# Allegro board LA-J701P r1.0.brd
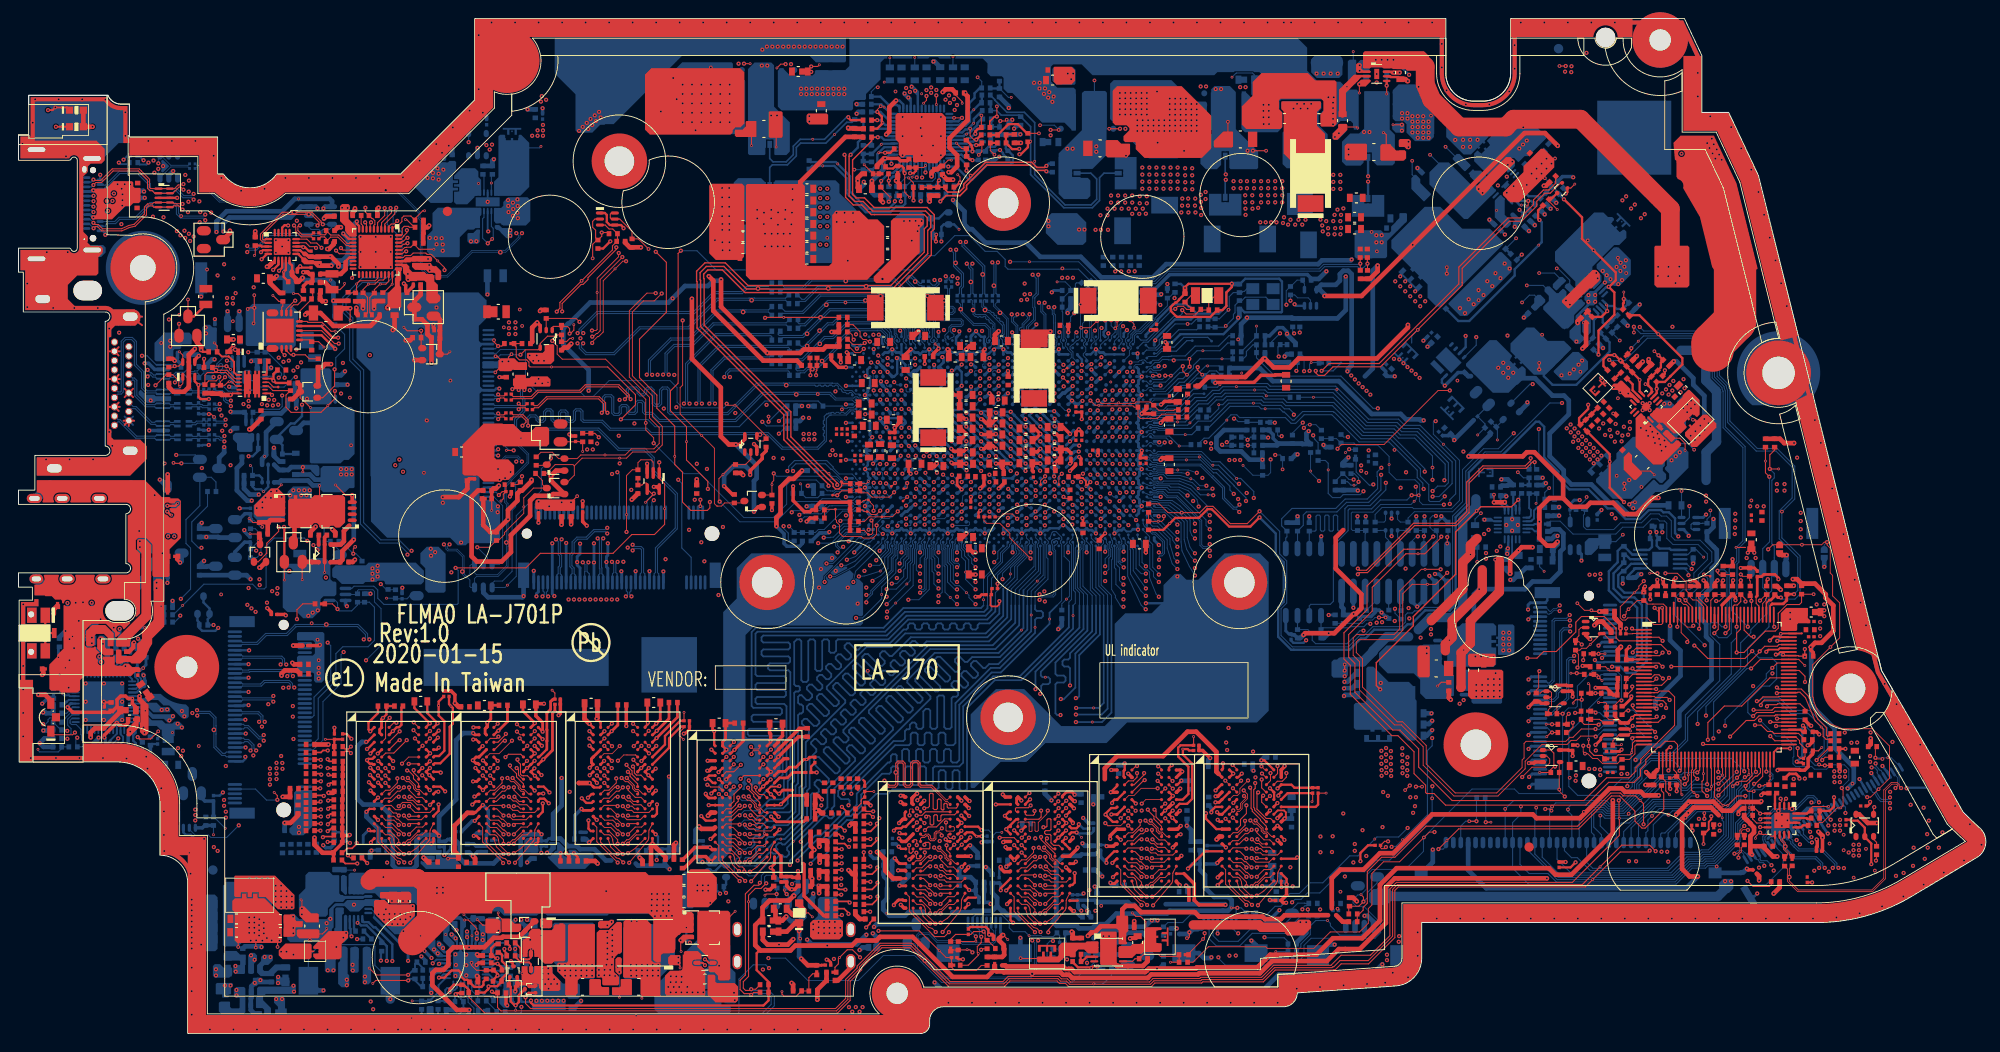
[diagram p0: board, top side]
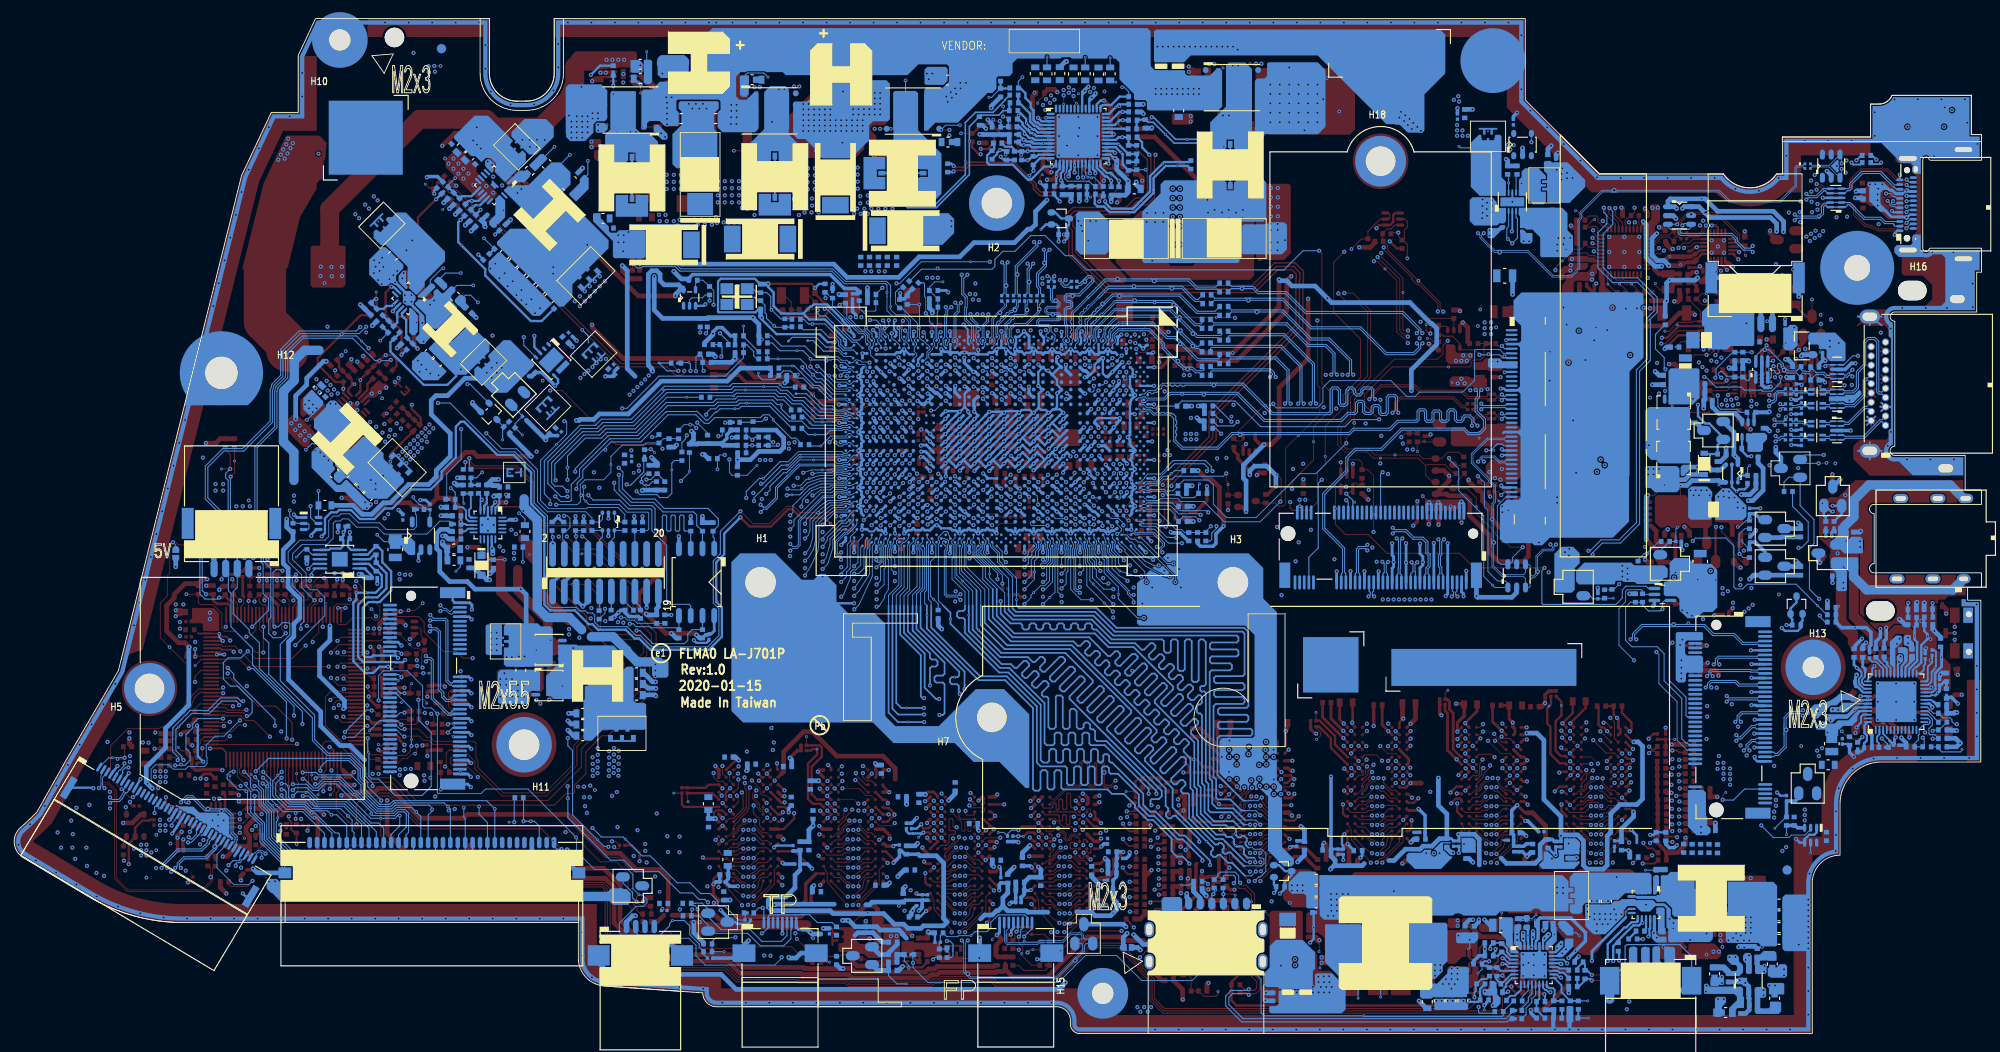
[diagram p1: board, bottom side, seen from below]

Outline 212.49 x 109.7 mm; copper layers: TOP, GND1, IN1, VCC, IN2, IN3, GND2, BOTTOM. Coordinates in mm from the lower left corner of the outline.

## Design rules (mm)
net group 8: nets EC_MUTE# PLUG_IN
net group AC: nets ACN ACP
net group DIFFPAIR12: nets N27490318 N27490324
net group DIFFPAIR13: nets VDDIO_MEM_S3_SENSE_H VDDIO_MEM_S3_SENSE_L
net group DIFFPAIR14: nets USBC0_SBU1_CONN USBC0_SBU2_CONN
net group EC_SMB_CK1: nets EC_SMB_CK1 EC_SMB_DA1
net group EC_SMB_CK2: nets EC_SMB_CK2 EC_SMB_DA2
net group I2C: nets USBC_I2C_SCL USBC_I2C_SDA
net group LPC-CLK: nets LPC_CLK0 LPC_CLK0_EC
net group PCIE_ARX_DTX_P7: nets PCIE_ARX_DTX_N7 PCIE_ARX_DTX_P7
net group PCIE_ATX_C_DRX_P7: nets PCIE_ATX_C_DRX_N7 PCIE_ATX_C_DRX_P7
net group PCIE_ATX_DRX_P7: nets PCIE_ATX_DRX_N7 PCIE_ATX_DRX_P7
net group REMOTE3: nets REMOTE3+ REMOTE3-
net group SINGLE-LED: nets BATT_CHG_LED# BATT_LOW_LED#
net group SINGLE-PROCHOT#: nets H_PROCHOT# VCOUT1_PROCHOT#
net group SINGLE-SVT: nets APU_SVT APU_SVT_R
net group SPK_L: nets SPK_L1- SPK_L2+
net group SPK_R: nets SPK_R1- SPK_R2+
net group SR: nets SRN SRP
net group 12.6VB_DDR: nets +12.6VB_DDR
net group 15: nets 3V/5VALW_PG 3V_FB 3V_FB_1 5V_3V_EN 5V_FB 5V_FB_1 EC_FAN_PWM1 EC_ON EC_RST# EC_RX EC_TX ENLDO_3V5V NOVO# TP_DISABLE# VCIN1_AC_IN
net group APU SENSE: nets APU_CORE_SEN_H APU_CORESOC_SEN_H APU_VDDP_S5_SEN_H APU_VDDP_S5_SEN_L APU_VSS_SEN_L
net group AUDIO: nets HPOUT_L1 HPOUT_R1 LDO2 LDO3 N31044849
net group CLK-PCIE: nets CLK_PCIE_SD CLK_PCIE_SD# CLK_PCIE_SSD1 CLK_PCIE_SSD1# CLK_PCIE_SSD2 CLK_PCIE_SSD2# CLK_PCIE_WLAN CLK_PCIE_WLAN#
net group CRYSTAL: nets 32K_X1 32K_X2 48M_X1 48M_X1_R 48M_X2 48M_X2_R RTC_CLK RTC_CLK_R SUSCLK_R
net group DDI-HDMI: nets APU_DP1_N0 APU_DP1_N1 APU_DP1_N2 APU_DP1_N3 APU_DP1_P0 APU_DP1_P1 APU_DP1_P2 APU_DP1_P3 HDMI_CLKN HDMI_CLKP HDMI_L_CLKN HDMI_L_CLKP HDMI_L_TX_N0 HDMI_L_TX_N1 HDMI_L_TX_N2 HDMI_L_TX_P0 HDMI_L_TX_P1 HDMI_L_TX_P2 HDMI_TX_N0 HDMI_TX_N1 HDMI_TX_N2 HDMI_TX_P0 HDMI_TX_P1 HDMI_TX_P2
net group DDR_A_CLK: nets DDR_A_CLK0#
net group DDR_A_CLK0: nets DDR_A_CLK0
net group DDR_A_CMD: nets DDR_A_ACT# DDR_A_BA0 DDR_A_BA1 DDR_A_BG0 DDR_A_BG1 DDR_A_BG1_R DDR_A_CAS# DDR_A_CKE0 DDR_A_CS0# DDR_A_MA0 DDR_A_MA1 DDR_A_MA2 DDR_A_MA3 DDR_A_MA4 DDR_A_MA5 DDR_A_MA6 DDR_A_MA7 DDR_A_MA8 DDR_A_MA9 DDR_A_MA10 DDR_A_MA11 DDR_A_MA12 DDR_A_MA13 DDR_A_ODT0 DDR_A_PAR DDR_A_RAS# DDR_A_WE#
net group DDR_A_DQ0: nets DDR_A_DM0 DDR_A_DQ0 DDR_A_DQ1 DDR_A_DQ2 DDR_A_DQ3 DDR_A_DQ4 DDR_A_DQ5 DDR_A_DQ6 DDR_A_DQ7
net group DDR_A_DQ1: nets DDR_A_DM1 DDR_A_DQ8 DDR_A_DQ9 DDR_A_DQ10 DDR_A_DQ11 DDR_A_DQ12 DDR_A_DQ13 DDR_A_DQ14 DDR_A_DQ15
net group DDR_A_DQ2: nets DDR_A_DM2 DDR_A_DQ16 DDR_A_DQ17 DDR_A_DQ18 DDR_A_DQ19 DDR_A_DQ20 DDR_A_DQ21 DDR_A_DQ22 DDR_A_DQ23
net group DDR_A_DQ3: nets DDR_A_DM3 DDR_A_DQ24 DDR_A_DQ25 DDR_A_DQ26 DDR_A_DQ27 DDR_A_DQ28 DDR_A_DQ29 DDR_A_DQ30 DDR_A_DQ31
net group DDR_A_DQ4: nets DDR_A_DM4 DDR_A_DQ32 DDR_A_DQ33 DDR_A_DQ34 DDR_A_DQ35 DDR_A_DQ36 DDR_A_DQ37 DDR_A_DQ38 DDR_A_DQ39
net group DDR_A_DQ5: nets DDR_A_DM5 DDR_A_DQ40 DDR_A_DQ41 DDR_A_DQ42 DDR_A_DQ43 DDR_A_DQ44 DDR_A_DQ45 DDR_A_DQ46 DDR_A_DQ47
net group DDR_A_DQ6: nets DDR_A_DM6 DDR_A_DQ48 DDR_A_DQ49 DDR_A_DQ50 DDR_A_DQ51 DDR_A_DQ52 DDR_A_DQ53 DDR_A_DQ54 DDR_A_DQ55
net group DDR_A_DQ7: nets DDR_A_DM7 DDR_A_DQ56 DDR_A_DQ57 DDR_A_DQ58 DDR_A_DQ59 DDR_A_DQ60 DDR_A_DQ61 DDR_A_DQ62 DDR_A_DQ63
net group DDR_A_DQS: nets DDR_A_DQS0# DDR_A_DQS1# DDR_A_DQS2# DDR_A_DQS3# DDR_A_DQS4# DDR_A_DQS5# DDR_A_DQS6# DDR_A_DQS7#
net group DDR_A_DQS0: nets DDR_A_DQS0
net group DDR_A_DQS1: nets DDR_A_DQS1
net group DDR_A_DQS2: nets DDR_A_DQS2
net group DDR_A_DQS3: nets DDR_A_DQS3
net group DDR_A_DQS4: nets DDR_A_DQS4
net group DDR_A_DQS5: nets DDR_A_DQS5
net group DDR_A_DQS6: nets DDR_A_DQS6
net group DDR_A_DQS7: nets DDR_A_DQS7
net group DDR_A_MISCELLANEOUS: nets DDR_A_ALERT# DDR_A_EVENT# DDR_A_RST#
net group DDR_B_CLK: nets DDR_B_CLK0#
net group DDR_B_CLK0: nets DDR_B_CLK0
net group DDR_B_CMD: nets DDR_B_ACT# DDR_B_BA0 DDR_B_BA1 DDR_B_BG0 DDR_B_BG1 DDR_B_BG1_R DDR_B_CAS# DDR_B_CKE0 DDR_B_CS0# DDR_B_MA0 DDR_B_MA1 DDR_B_MA2 DDR_B_MA3 DDR_B_MA4 DDR_B_MA5 DDR_B_MA6 DDR_B_MA7 DDR_B_MA8 DDR_B_MA9 DDR_B_MA10 DDR_B_MA11 DDR_B_MA12 DDR_B_MA13 DDR_B_ODT0 DDR_B_PAR DDR_B_RAS# DDR_B_WE#
net group DDR_B_DQ0: nets DDR_B_DM0 DDR_B_DQ0 DDR_B_DQ1 DDR_B_DQ2 DDR_B_DQ3 DDR_B_DQ4 DDR_B_DQ5 DDR_B_DQ6 DDR_B_DQ7
net group DDR_B_DQ1: nets DDR_B_DM1 DDR_B_DQ8 DDR_B_DQ9 DDR_B_DQ10 DDR_B_DQ11 DDR_B_DQ12 DDR_B_DQ13 DDR_B_DQ14 DDR_B_DQ15
net group DDR_B_DQ2: nets DDR_B_DM2 DDR_B_DQ16 DDR_B_DQ17 DDR_B_DQ18 DDR_B_DQ19 DDR_B_DQ20 DDR_B_DQ21 DDR_B_DQ22 DDR_B_DQ23
net group DDR_B_DQ3: nets DDR_B_DM3 DDR_B_DQ24 DDR_B_DQ25 DDR_B_DQ26 DDR_B_DQ27 DDR_B_DQ28 DDR_B_DQ29 DDR_B_DQ30 DDR_B_DQ31
net group DDR_B_DQ4: nets DDR_B_DM4 DDR_B_DQ32 DDR_B_DQ33 DDR_B_DQ34 DDR_B_DQ35 DDR_B_DQ36 DDR_B_DQ37 DDR_B_DQ38 DDR_B_DQ39
net group DDR_B_DQ5: nets DDR_B_DM5 DDR_B_DQ40 DDR_B_DQ41 DDR_B_DQ42 DDR_B_DQ43 DDR_B_DQ44 DDR_B_DQ45 DDR_B_DQ46 DDR_B_DQ47
net group DDR_B_DQ6: nets DDR_B_DM6 DDR_B_DQ48 DDR_B_DQ49 DDR_B_DQ50 DDR_B_DQ51 DDR_B_DQ52 DDR_B_DQ53 DDR_B_DQ54 DDR_B_DQ55
net group DDR_B_DQ7: nets DDR_B_DM7 DDR_B_DQ56 DDR_B_DQ57 DDR_B_DQ58 DDR_B_DQ59 DDR_B_DQ60 DDR_B_DQ61 DDR_B_DQ62 DDR_B_DQ63
net group DDR_B_DQS: nets DDR_B_DQS0# DDR_B_DQS1# DDR_B_DQS2# DDR_B_DQS3# DDR_B_DQS4# DDR_B_DQS5# DDR_B_DQS6# DDR_B_DQS7#
net group DDR_B_DQS0: nets DDR_B_DQS0
net group DDR_B_DQS1: nets DDR_B_DQS1
net group DDR_B_DQS2: nets DDR_B_DQS2
net group DDR_B_DQS3: nets DDR_B_DQS3
net group DDR_B_DQS4: nets DDR_B_DQS4
net group DDR_B_DQS5: nets DDR_B_DQS5
net group DDR_B_DQS6: nets DDR_B_DQS6
net group DDR_B_DQS7: nets DDR_B_DQS7
net group DDR_B_MISCELLANEOUS: nets DDR_B_ALERT# DDR_B_EVENT# DDR_B_RST#
net group DP-AUX: nets APU_DP1_CTRL_CLK APU_DP1_CTRL_DAT EDP_AUXN EDP_AUXN_C EDP_AUXP EDP_AUXP_C HDMI_CTRL_CLK HDMI_CTRL_DAT USBC0_AUXN USBC0_AUXP USBC0_C_AUXN USBC0_C_AUXP USBC0_SBU1 USBC0_SBU2
net group EDP: nets EDP_TXN0 EDP_TXN0_C EDP_TXN1 EDP_TXN1_C EDP_TXP0 EDP_TXP0_C EDP_TXP1 EDP_TXP1_C
net group HDA: nets HDA_BIT_CLK HDA_BIT_CLK_R HDA_RST# HDA_SDIN0 HDA_SDIN0_R HDA_SDOUT HDA_SDOUT_R HDA_SYNC HDA_SYNC_R
net group HP: nets HP_OUTL HP_OUTR HPOUT_L HPOUT_R
net group LED: nets BATT_CHG_LED#_R2 BATT_LOW_LED#_R2 CAPS_LED#
net group LPC: nets CLKRUN# EC_SCI# LPC_AD0 LPC_AD0_R LPC_AD1 LPC_AD1_R LPC_AD2 LPC_AD2_R LPC_AD3 LPC_AD3_R LPC_FRAME# LPC_RST# LPC_RST#_R LPCPD# SERIRQ
net group PCIE: nets PCIE_ARX_DTX_N0 PCIE_ARX_DTX_N1 PCIE_ARX_DTX_N2 PCIE_ARX_DTX_N3 PCIE_ARX_DTX_N8 PCIE_ARX_DTX_N9 PCIE_ARX_DTX_N10 PCIE_ARX_DTX_N11 PCIE_ARX_DTX_P0 PCIE_ARX_DTX_P1 PCIE_ARX_DTX_P2 PCIE_ARX_DTX_P3 PCIE_ARX_DTX_P8 PCIE_ARX_DTX_P9 PCIE_ARX_DTX_P10 PCIE_ARX_DTX_P11 PCIE_ATX_C_DRX_N0 PCIE_ATX_C_DRX_N1 PCIE_ATX_C_DRX_N2 PCIE_ATX_C_DRX_N3 PCIE_ATX_C_DRX_N8 PCIE_ATX_C_DRX_N9 PCIE_ATX_C_DRX_N10 PCIE_ATX_C_DRX_N11 PCIE_ATX_C_DRX_P0 PCIE_ATX_C_DRX_P1 PCIE_ATX_C_DRX_P2 PCIE_ATX_C_DRX_P3 PCIE_ATX_C_DRX_P8 PCIE_ATX_C_DRX_P9 PCIE_ATX_C_DRX_P10 PCIE_ATX_C_DRX_P11 PCIE_ATX_DRX_N0 PCIE_ATX_DRX_N1 PCIE_ATX_DRX_N2 PCIE_ATX_DRX_N3 PCIE_ATX_DRX_N8 PCIE_ATX_DRX_N9 PCIE_ATX_DRX_N10 PCIE_ATX_DRX_N11 PCIE_ATX_DRX_P0 PCIE_ATX_DRX_P1 PCIE_ATX_DRX_P2 PCIE_ATX_DRX_P3 PCIE_ATX_DRX_P8 PCIE_ATX_DRX_P9 PCIE_ATX_DRX_P10 PCIE_ATX_DRX_P11
net group PCIE-ONBOARD: nets PCIE_ARX_DTX_N5 PCIE_ARX_DTX_P5 PCIE_ATX_C_DRX_N5 PCIE_ATX_C_DRX_P5 PCIE_ATX_DRX_N5 PCIE_ATX_DRX_P5
net group S20: nets PWR_LED#
net group SINGLE-ALERT: nets APU_ALERT#
net group SINGLE-BEEP: nets BEEP# HDA_SPKR PC_BEEP
net group SINGLE-BT/WLAN: nets APU_BT_OFF# APU_WL_OFF# WL_RST#
net group SINGLE-DISPLAY: nets ENBKL ENBKL_R ENVDD INVTPWM INVTPWM_R
net group SINGLE-DMIC: nets DMIC_CLK0_APU DMIC_DAT0_APU SOC_DMIC_CLK0 SOC_DMIC_DAT0
net group SINGLE-DP: nets APU_DP1_HPD EDP_HPD EDP_HPD_R HDMI_HPD USBC0_PD_HPD
net group SINGLE-HDT: nets APU_DBREQ# APU_TCK APU_TDI APU_TDO APU_TMS APU_TRST# APU_TRST#_R
net group SINGLE-KB: nets KB_RST#
net group SINGLE-PCIE_REQ: nets CLKREQ_SD# CLKREQ_SSD1# CLKREQ_WLAN# CLKREQ_WLAN#_R
net group SINGLE-SENSOR: nets LID_SW#
net group SINGLE-SEQUENCE: nets AC_PRESENT APU_FCH_PWRGD_R APU_PCIE0_RST# APU_PCIE1_RST# APU_PCIE_RST# APU_PCIE_RST#_R APU_PCIE_WAKE# APU_PWRGD APU_RST# APU_RST#_EC EC_LOW_BATT# EC_RSMRST# EC_THERMTRIP# FP_GPIO_AL0 ON/OFF# PBTN_OUT# PM_SLP_S3# PM_SLP_S5# S0A3_GPIO S0I3_EC# SSD1_PWR_EN# SSD2_PWR_EN# SUSP# SYS_PWRGD_EC SYS_RESET# VR_ON
net group SINGLE-SVC: nets APU_SVC
net group SINGLE-SVD: nets APU_SVD
net group SINGLE-TEST POINT: nets APU_TEST4 APU_TEST5 APU_TEST14 APU_TEST15 APU_TEST16 APU_TEST17 APU_TEST31 APU_TEST41 APU_TEST470 APU_TEST471
net group SINGLE-USB_OC: nets USB_OC0# USB_OC0#_R USB_OC1#
net group SMBUS: nets EC_SMCA EC_SMDA SCL_CHG SDA_CHG
net group SPI: nets APU_SPI_CLK APU_SPI_CLK_R APU_SPI_CS1# APU_SPI_HOLD# APU_SPI_MISO APU_SPI_MOSI APU_SPI_WP#
net group SPK: nets SPK_L1-_CONN SPK_L2+_CONN SPK_R1-_CONN SPK_R2+_CONN
net group USB-20: nets CHR_USB20_N1 CHR_USB20_N1_R CHR_USB20_P1 CHR_USB20_P1_R USB20_N1 USB20_N2 USB20_N3 USB20_N5 USB20_N5_R USB20_N6 USB20_N7 USB20_P1 USB20_P2 USB20_P3 USB20_P5 USB20_P5_R USB20_P6 USB20_P7
net group USB-32: nets USBC0_ARX_C_DTX_N1 USBC0_ARX_C_DTX_N2 USBC0_ARX_C_DTX_P1 USBC0_ARX_C_DTX_P2 USBC0_ARX_DTX_N1 USBC0_ARX_DTX_N2 USBC0_ARX_DTX_P1 USBC0_ARX_DTX_P2 USBC0_ATX_C_DRX_N1 USBC0_ATX_C_DRX_N2 USBC0_ATX_C_DRX_P1 USBC0_ATX_C_DRX_P2 USBC0_ATX_DRX_N1 USBC0_ATX_DRX_N2 USBC0_ATX_DRX_P1 USBC0_ATX_DRX_P2
net group USB-C20: nets USB20_N0 USB20_N0_R USB20_P0 USB20_P0_R
net group USB-C31: nets USB3_ARX_DTX_N1 USB3_ARX_DTX_N2 USB3_ARX_DTX_P1 USB3_ARX_DTX_P2 USB3_ATX_DRX_N1 USB3_ATX_DRX_N2 USB3_ATX_DRX_P1 USB3_ATX_DRX_P2
net group W10S10: nets REMOTE1+ REMOTE2+ REMOTE-
net group W20: nets +1.8VALWP
net group W40: nets EXT_MIC_RING2 EXT_MIC_SLEEVE HGNDA HGNDB N31049415 N31049464
nets with their own width: min track width 0.102; nets SYSON
nets with their own width: min track width 0.254; nets +0.6VS +1.2V +3VL +APU_CORE ECAGND GND
nets with their own width: min track width 0.305; nets +1.8VDD_CODEC
nets with their own width: min track width 0.508; nets +0.6V_DDRB_VREFCA +0.75VALW +0.75VALW_0.75VS +0.75VALWP +0.75VS +1.2VP +1.8VALW +1.8VALW_1.8VS +1.8VS +2.5V +3V_DMIC +3V_FP +3VALW +3VALW_EC +3VDD_CODEC +3VS +3VS_SSD2 +3VS_TP +5V_IN_PWR +5VL +5VS_KBL +12.6VB_3V +12.6VB_5V +12.6VB_CPU +12.6VB_VDDP +19V_ADPIN +19V_VIN_P1 +20V_TBT_VBUS_L +APU_CORE_SOC +FLT1 +IOVDD_CODEC +LDO_3V3_5457V +LEDVDD +RTC_APU +RTCBATT +RTCBATT_R +USBC0_VBUS +VCC_IO2 GNDA VDDIO_AUDIO
nets with their own width: min track width 1.016; nets +0.6V_DDRA_VREFCA +5V_DISPLAY +5VALW_USB2 +5VS_FAN +5VS_PVDD +LCDVDD
nets with their own width: min track width 1.524; nets +LCDVDD_CONN
nets with their own width: min track width 2.032; nets +3VS_SSD1 +3VS_WLAN +5VDDA_CODEC
nets with their own width: min track width 2.54; nets +5VALW_USB1

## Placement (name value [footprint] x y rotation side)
C1  1U_0201_6.3V6M  [C_0201]  113.68 62.15 90 top
C3  4.7U_0402_6.3V6M  [C_0402]  52.68 71.85 270 top
C4  1U_0201_6.3V6M  [C_0201]  50.56 98.21 90 bottom
C7  4.7U_0805_25V6-K  [C_0805]  52.35 81.89 180 bottom
C8  0.1U_0201_10V6K  [C_0201]  53.23 66.44 180 top
C9  0.1U_0201_10V6K  [C_0201]  53.23 67.07 180 top
C10  0.1U_0201_10V6K  [C_0201]  55.52 67.43 180 top
C11  0.1U_0201_10V6K  [C_0201]  55.52 68.06 180 top
C12  0.1U_0201_10V6K  [C_0201]  53.23 69.11 180 top
C13  0.1U_0201_10V6K  [C_0201]  53.23 68.47 180 top
C67  0.1U_0201_10V6K  [C_0201]  192.8 29.74 270 top
C68  1000P_0402_50V7K  [C_0402]  176.64 27.78 270 top
C69  1000P_0402_50V7K  [C_0402]  173.66 40.4 180 top
C70  0.1U_0201_10V6K  [C_0201]  178.35 27.03 90 top
C71  0.1U_0201_10V6K  [C_0201]  51.69 87.76 270 bottom
C72  10U_0402_6.3V6M  [C_0402]  52.45 87.67 270 bottom
C73  10U_0402_6.3V6M  [C_0402]  55.82 98.96 90 bottom
C74  0.1U_0201_10V6K  [C_0201]  56.61 98.82 90 bottom
C75  1000P_0402_50V7K  [C_0402]  51.18 92.86 90 bottom
C76  2200P_0402_25V7K  [C_0402]  50.17 92.86 90 bottom
C77  0.1U_0201_10V6K  [C_0201]  49.66 87.25 270 bottom
C78  10U_0402_6.3V6M  [C_0402]  48.9 87.17 270 bottom
C79  10U_0402_6.3V6M  [C_0402]  46.84 94.05 90 bottom
C80  0.1U_0201_10V6K  [C_0201]  45.95 93.96 90 bottom
C84  4.7U_0402_6.3V6M  [C_0402]  177.02 47.44 90 top
C204  0.1U_0201_10V6K  [C_0201]  60.18 63.99 90 top
C229  0.1U_0201_10V6K  [C_0201]  181.31 22.51 180 top
C230  0.1U_0201_10V6K  [C_0201]  49.25 60.53 270 top
C231  10U_0402_6.3V6M  [C_0402]  48.48 60.66 270 top
C232  100P_0402_50V8J  [C_0402]  186.99 49.41 90 top
C233  0.1U_0201_10V6K  [C_0201]  176.25 47.48 90 top
C234  100P_0402_50V8J  [C_0402]  185.14 47.44 90 top
C235  0.1U_0201_10V6K  [C_0201]  193.36 44.53 0 top
C236  10U_0402_6.3V6M  [C_0402]  153.27 75.31 225 bottom
C237  0.1U_0201_10V K X5R  [C_0201]  152.62 75.75 225 bottom
C238  10U_0402_6.3V6M  [C_0402]  156.85 72.08 225 bottom
C239  0.1U_0201_10V K X5R  [C_0201]  157.3 71.46 225 bottom
C240  10U_0402_6.3V6M  [C_0402]  154.02 65.45 315 bottom
C241  0.1U_0201_10V K X5R  [C_0201]  153.4 65.03 315 bottom
C242  10U_0402_6.3V6M  [C_0402]  148.32 71.83 225 bottom
C243  0.1U_0201_10V K X5R  [C_0201]  147.75 72.32 225 bottom
C249  27P_0201_25V8  [C_0201]  52.65 58.57 0 top
C250  0.22U_0201_6.3V6M  [C_0201]  102.67 79.15 90 bottom
C251  0.22U_0201_6.3V6M  [C_0201]  103.34 79.16 90 bottom
C252  0.22U_0201_6.3V6M  [C_0201]  105.83 79.16 90 bottom
C253  0.22U_0201_6.3V6M  [C_0201]  105.2 79.16 90 bottom
C255  100P_0402_50V8J  [C_0402]  184.13 49.6 90 top
C256  220P_0201_25V7K  [C_0201]  173.63 43.2 180 top
C257  100P_0402_50V8J  [C_0402]  189.08 26.89 270 top
C258  0.1U_0201_10V K X5R  [C_0201]  187.81 49.97 270 top
C259  100P_0402_50V8J  [C_0402]  173.66 38.37 180 top
C260  100P_0402_50V8J  [C_0402]  173.21 29.62 270 top
C261  100P_0402_50V8J  [C_0402]  188.83 47.44 90 top
C265  100P_0402_50V8J  [C_0402]  183.24 47.44 90 top
C266  220P_0201_25V7K  [C_0201]  193.36 42.88 0 top
C267  100P_0402_50V8J  [C_0402]  181.46 48.35 270 top
C268  22P_0402_50V8J  [C_0402]  170.68 39.64 180 top
C269  0.1U_0201_10V6K  [C_0201]  171.53 30.49 0 top
C316  0.1U_0201_10V K X5R  [C_0201]  157.59 66.7 225 bottom
C317  100P_0402_50V8J  [C_0402]  196.65 29.86 180 top
C318  100P_0402_50V8J  [C_0402]  196.65 30.77 180 top
CA1  22P_0402_50V8J  [C_0402]  4.65 30.98 180 bottom
CA2  1000P_0402_50V7K  [C_0402]  24.17 3.05 0 bottom
CA3  1000P_0402_50V7K  [C_0402]  26 3.08 270 bottom
CA4  1000P_0402_50V7K  [C_0402]  24.22 8.26 90 bottom
CA5  1000P_0402_50V7K  [C_0402]  27.32 6.48 270 bottom
CA6  2.2U_0402_6.3V6M  [C_0402]  3.79 38.04 90 bottom
CA7  2.2U_0402_6.3V6M  [C_0402]  12.83 41.57 270 bottom
CA8  2.2U_0402_6.3V6M  [C_0402]  13.77 41.57 270 bottom
CA9  2.2U_0402_6.3V6M  [C_0402]  10.52 41.62 270 bottom
CA10  1U_0201_6.3V6M  [C_0201]  6.07 41.08 270 bottom
CA11  1U_0201_6.3V6M  [C_0201]  5.34 40.86 90 bottom
CA12  4.7U_0402_6.3V6M  [C_0402]  14.25 32.07 270 bottom
CA13  0.1U_0201_10V6K  [C_0201]  15.03 31.87 270 bottom
CA14  2.2U_0402_6.3V6M  [C_0402]  4.42 42.7 270 bottom
CA15  2.2U_0402_6.3V6M  [C_0402]  3.76 35.53 0 bottom
CA16  1000P_0402_50V7K  [C_0402]  10.82 40.28 180 top
CA17  1000P_0402_50V7K  [C_0402]  11.69 42.18 270 top
CA18  220P_0402_50V7K  [C_0402]  7.04 45.81 0 bottom
CA19  220P_0402_50V7K  [C_0402]  6.2 45.84 180 bottom
CA20  0.1U_0201_10V6K  [C_0201]  12.88 38.73 90 top
CA21  0.1U_0201_10V6K  [C_0201]  9.26 34.71 90 top
CA22  0.1U_0201_10V6K  [C_0201]  9.5 31.16 180 bottom
CA24  0.1U_0201_10V6K  [C_0201]  4.52 37.67 90 bottom
CA25  0.1U_0201_10V6K  [C_0201]  12.09 41.15 270 bottom
CA28  2.2U_0402_6.3V6M  [C_0402]  10 34.87 90 top
CA30  2.2P_0402_50V8C  [C_0402]  4.65 31.9 180 bottom
CA31  2.2P_0402_50V8C  [C_0402]  7.22 30.98 0 bottom
CA32  2.2P_0402_50V8C  [C_0402]  4.65 34.61 180 bottom
CA33  2.2P_0402_50V8C  [C_0402]  4.65 32.81 180 bottom
CA35  2200P_0402_25V7K  [C_0402]  16.11 49.42 180 bottom
CA50  0.1U_0201_10V6K  [C_0201]  25.02 53.1 90 bottom
CA51  0.1U_0201_10V6K  [C_0201]  21.06 25.13 90 bottom
CA52  0.1U_0201_10V6K  [C_0201]  25.06 56.18 90 bottom
CC1  0.22U_0402_6.3V6K  [C_0402]  84.19 76.22 180 bottom
CC2  0.22U_0402_6.3V6K  [C_0402]  84.19 77.17 180 bottom
CC3  0.22U_0402_6.3V6K  [C_0402]  82.29 77.62 180 bottom
CC4  0.22U_0402_6.3V6K  [C_0402]  82.29 78.57 180 bottom
CC5  0.22U_0402_6.3V6K  [C_0402]  84.13 78.89 180 bottom
CC6  0.22U_0402_6.3V6K  [C_0402]  84.13 79.84 180 bottom
CC7  0.22U_0402_6.3V6K  [C_0402]  82.29 80.16 180 bottom
CC8  0.22U_0402_6.3V6K  [C_0402]  82.29 81.11 180 bottom
CC9  0.1U_0201_10V6K  [C_0201]  97.72 81.3 0 bottom
CC10  0.1U_0201_10V6K  [C_0201]  97.72 80.66 0 bottom
CC11  0.1U_0201_10V6K  [C_0201]  100.79 80.69 90 bottom
CC12  0.1U_0201_10V6K  [C_0201]  100.16 80.69 90 bottom
CC17  100P_0402_50V8J  [C_0402]  85.63 53.23 90 bottom
CC18  100P_0402_50V8J  [C_0402]  120.34 79.88 180 bottom
CC19  100P_0402_50V8J  [C_0402]  124.92 81.02 270 bottom
CC20  150P_0402_50V8J  [C_0402]  141.77 63.38 90 bottom
CC22  0.1U_0201_10V6K  [C_0201]  121.95 79.95 270 bottom
CC23  100P_0402_50V8J  [C_0402]  137.51 73.42 0 bottom
CC24  100P_0402_50V8J  [C_0402]  113.64 79.39 180 bottom
CC26  0.1U_0201_10V6K  [C_0201]  167.75 37 90 top
CC27  2P_0402_50V  [C_0402]  131.88 79.22 270 bottom
CC28  2P_0402_50V  [C_0402]  131.88 80.08 90 bottom
CC29  150P_0402_50V8J  [C_0402]  172.7 36.59 0 top
CC30  8.2P_0402_50V  [C_0402]  126 79.05 90 top
CC31  8.2P_0402_50V  [C_0402]  128.57 78.19 0 top
CC32  0.1U_0201_10V6K  [C_0201]  137.46 43.17 270 bottom
CC33  10P_0402_50V8J  [C_0402]  133.72 75.41 0 bottom
CC35  22U_0603_6.3V6M  [C_0603]  74.97 33.55 0 top
CC36  22U_0603_6.3V6M  [C_0603]  61.14 35.69 0 top
CC37  22U_0603_6.3V6M  [C_0603]  44.16 35.9 180 top
CC38  22U_0603_6.3V6M  [C_0603]  49.62 35.45 0 top
CC39  22U_0603_6.3V6M  [C_0603]  82.53 33.48 180 top
CC40  22U_0603_6.3V6M  [C_0603]  69.32 35.77 180 top
CC43  1U_0201_6.3V6M  [C_0201]  109.62 60.14 90 top
CC44  1U_0201_6.3V6M  [C_0201]  102.86 56.86 90 top
CC45  180P_0402_50V8J  [C_0402]  114.98 54.11 90 top
CC46  180P_0402_50V8J  [C_0402]  38.83 35.39 0 top
CC47  180P_0402_50V8J  [C_0402]  116.73 52.38 90 top
CC48  .22U 6.3V K X5R 0402  [C_0402]  37.07 19.08 0 bottom
CC49  .22U 6.3V K X5R 0402  [C_0402]  44.67 19.87 270 bottom
CC50  .22U 6.3V K X5R 0402  [C_0402]  55.69 19.82 270 bottom
CC51  .22U 6.3V K X5R 0402  [C_0402]  67.81 19.77 180 bottom
CC52  22U_0603_6.3V6M  [C_0603]  55.88 35.57 180 top
CC53  22U_0603_6.3V6M  [C_0603]  91.86 63.65 270 top
CC54  22U_0603_6.3V6M  [C_0603]  94.34 63.58 270 top
CC55  1U_0201_6.3V6M  [C_0201]  94.09 64.37 90 top
CC56  1U_0201_6.3V6M  [C_0201]  88.94 64.76 90 top
CC57  1U_0201_6.3V6M  [C_0201]  94.66 64.37 90 top
CC58  1U_0201_6.3V6M  [C_0201]  88.36 64.76 90 top
CC59  1U_0201_6.3V6M  [C_0201]  90.97 62.48 270 top
CC60  1U_0201_6.3V6M  [C_0201]  90.34 62.48 270 top
CC61  1U_0201_6.3V6M  [C_0201]  88.81 62.48 270 top
CC62  1U_0201_6.3V6M  [C_0201]  89.51 64.75 90 top
CC63  180P_0402_50V8J  [C_0402]  90.28 64.58 90 top
CC64  22U_0603_6.3V6M  [C_0603]  124.06 75.39 270 top
CC65  1U_0201_6.3V6M  [C_0201]  122.93 76.65 270 top
CC66  1U_0201_6.3V6M  [C_0201]  114.21 67.75 270 top
CC67  1U_0201_6.3V6M  [C_0201]  114.85 67.75 270 top
CC68  22U_0603_6.3V6M  [C_0603]  125.21 69.66 270 top
CC69  1U_0201_6.3V6M  [C_0201]  124.32 68.9 270 top
CC70  22U_0603_6.3V6M  [C_0603]  124.31 60.79 90 top
CC71  1U_0201_6.3V6M  [C_0201]  121.16 61.63 90 top
CC72  1U_0201_6.3V6M  [C_0201]  121.8 61.63 90 top
CC73  22U_0603_6.3V6M  [C_0603]  136.92 69.79 90 top
CC74  1U_0201_6.3V6M  [C_0201]  114.76 61.55 180 top
CC75  22U_0603_6.3V6M  [C_0603]  124.31 65.04 90 top
CC76  1U_0201_6.3V6M  [C_0201]  114.21 64.11 90 top
CC77  1U_0201_6.3V6M  [C_0201]  114.85 64.11 90 top
CC78  10U_0402_6.3V6M  [C_0402]  146.57 62.54 270 bottom
CC79  1U_0201_6.3V6M  [C_0201]  116.03 63.05 0 top
CC80  1U_0201_6.3V6M  [C_0201]  145.81 62.4 270 bottom
CC81  0.22U_0402_6.3V6K  [C_0402]  84.59 4.6 180 top
CC82  1U_0201_6.3V6M  [C_0201]  87.15 7.4 0 top
CC105  0.22U_0402_6.3V6K  [C_0402]  87.28 5.73 0 top
CC106  0.22U_0402_6.3V6K  [C_0402]  84.19 73.68 180 bottom
CC107  0.22U_0402_6.3V6K  [C_0402]  84.19 74.63 180 bottom
CC108  0.22U_0402_6.3V6K  [C_0402]  84.19 71.14 180 bottom
CC109  0.22U_0402_6.3V6K  [C_0402]  82.29 75.9 180 bottom
CC110  0.22U_0402_6.3V6K  [C_0402]  82.29 74.95 180 bottom
CC111  0.22U_0402_6.3V6K  [C_0402]  84.19 72.09 180 bottom
CC112  0.22U_0402_6.3V6K  [C_0402]  82.29 73.39 180 bottom
CC113  0.22U_0402_6.3V6K  [C_0402]  82.29 72.41 180 bottom
CC114  0.1U_0201_10V6K  [C_0201]  167.87 30.59 90 top
CC115  22U_0603_6.3V6M  [C_0603]  93.07 63.71 270 top
CC116  22U_0603_6.3V6M  [C_0603]  120.37 52.91 0 top
CC117  22U_0603_6.3V6M  [C_0603]  104.05 49.61 180 top
CC118  22U_0603_6.3V6M  [C_0603]  104.05 52.44 180 top
CC119  22U_0603_6.3V6M  [C_0603]  103.1 53.65 180 top
CD1  .047U_0402_16V7K  [C_0402]  105.17 16.26 90 bottom
CD2  .047U_0402_16V7K  [C_0402]  93.44 17.33 0 bottom
CD3  0.1U_0201_10V6K  [C_0201]  91.41 26.74 270 top
CD4  0.1U_0201_10V6K  [C_0201]  91.41 24.96 90 top
CD5  0.1U_0201_10V6K  [C_0201]  94.4 20.49 90 bottom
CD6  0.1U_0201_10V6K  [C_0201]  92.76 18.93 0 bottom
CD7  0.1U_0201_10V6K  [C_0201]  128.2 18.32 180 bottom
CD8  .047U_0402_16V7K  [C_0402]  127.61 19.82 90 bottom
CD9  .047U_0402_16V7K  [C_0402]  116.12 19.37 90 bottom
CD10  0.22U_0402_6.3V6K  [C_0402]  105.93 18.73 0 bottom
CD11  0.22U_0402_6.3V6K  [C_0402]  117.03 25.58 180 bottom
CD12  0.22U_0402_6.3V6K  [C_0402]  135.77 29.88 180 bottom
CD13  0.22U_0402_6.3V6K  [C_0402]  101.62 15.98 90 bottom
CD14  0.22U_0402_6.3V6K  [C_0402]  114.93 12.6 0 bottom
CD15  0.22U_0402_6.3V6K  [C_0402]  125.37 15.32 0 bottom
CD16  0.22U_0402_6.3V6K  [C_0402]  135.86 15.33 270 bottom
CD17  0.22U_0402_6.3V6K  [C_0402]  103.6 18.12 90 bottom
CD18  0.22U_0402_6.3V6K  [C_0402]  126.66 19.82 90 bottom
CD19  0.22U_0402_6.3V6K  [C_0402]  115.22 17.67 0 bottom
CD20  0.22U_0402_6.3V6K  [C_0402]  118.84 28.1 90 bottom
CD21  0.22U_0402_6.3V6K  [C_0402]  110.86 27.13 270 bottom
CD22  0.22U_0402_6.3V6K  [C_0402]  96.12 18.06 270 bottom
CD23  0.22U_0402_6.3V6K  [C_0402]  137.51 22.31 90 bottom
CD24  0.22U_0402_6.3V6K  [C_0402]  129.43 28.86 180 bottom
CD25  0.22U_0402_6.3V6K  [C_0402]  132.4 29.11 0 bottom
CD26  0.22U_0402_6.3V6K  [C_0402]  114.77 24.95 90 bottom
CD27  0.22U_0402_6.3V6K  [C_0402]  126.51 26.4 90 bottom
CD28  0.22U_0402_6.3V6K  [C_0402]  86.48 20.85 180 top
CD29  0.22U_0402_6.3V6K  [C_0402]  86.48 15.89 180 top
CD30  0.22U_0402_6.3V6K  [C_0402]  86.48 17.61 180 top
CD31  0.22U_0402_6.3V6K  [C_0402]  86.54 19.2 180 top
CD32  0.22U_0402_6.3V6K  [C_0402]  87.81 23.83 180 top
CD33  0.22U_0402_6.3V6K  [C_0402]  88.85 27.54 270 top
CD34  0.1U_0201_10V6K  [C_0201]  105.93 16.26 90 bottom
CD35  0.22U_0402_6.3V6K  [C_0402]  87.96 27.09 270 top
CD36  0.1U_0201_10V6K  [C_0201]  93.81 16.57 0 bottom
CD37  0.22U_0402_6.3V6K  [C_0402]  89.74 27.54 270 top
CD38  0.1U_0201_10V6K  [C_0201]  116.88 19.79 90 bottom
CD39  0.22U_0402_6.3V6K  [C_0402]  90.63 27.54 270 top
CD40  0.1U_0201_10V6K  [C_0201]  128.38 19.73 90 bottom
CD41  0.22U_0402_6.3V6K  [C_0402]  87.06 27.09 270 top
CD42  1U_0201_6.3V6M  [C_0201]  104.32 14.71 180 bottom
CD43  1U_0201_6.3V6M  [C_0201]  104.32 14.15 180 bottom
CD44  10U 6.3V M X5R 0402  [C_0402]  104.31 15.45 180 bottom
CD45  1U_0201_6.3V6M  [C_0201]  113.83 14.41 90 bottom
CD46  1U_0201_6.3V6M  [C_0201]  114.41 14.41 90 bottom
CD47  10U 6.3V M X5R 0402  [C_0402]  116.48 14.2 90 bottom
CD48  1U_0201_6.3V6M  [C_0201]  136.38 14.38 180 top
CD49  1U_0201_6.3V6M  [C_0201]  127 14.41 180 top
CD50  10U 6.3V M X5R 0402  [C_0402]  104.31 16.34 180 bottom
CD51  1U_0201_6.3V6M  [C_0201]  136.27 16.39 180 bottom
CD52  1U_0201_6.3V6M  [C_0201]  114.43 13.82 0 bottom
CD53  10U 6.3V M X5R 0402  [C_0402]  136.29 17.15 180 bottom
CD54  0.1U_0201_10V6K  [C_0201]  35.01 32.38 270 top
CD55  0.1U_0201_10V6K  [C_0201]  34.12 32.38 270 top
CD56  0.1U_0201_10V6K  [C_0201]  47.84 21.81 180 bottom
CD57  0.1U_0201_10V6K  [C_0201]  50.54 19.65 90 bottom
CD58  0.1U_0201_10V6K  [C_0201]  49.95 19.65 90 bottom
CD59  .047U_0402_16V7K  [C_0402]  38.89 20.73 270 bottom
CD60  .047U_0402_16V7K  [C_0402]  60.06 21.01 0 bottom
CD61  .047U_0402_16V7K  [C_0402]  50.74 21.7 180 bottom
CD62  .047U_0402_16V7K  [C_0402]  73.13 20.73 270 bottom
CD63  0.22U_0402_6.3V6K  [C_0402]  60.39 18.65 0 top
CD64  0.22U_0402_6.3V6K  [C_0402]  85.2 32.99 270 top
CD65  0.22U_0402_6.3V6K  [C_0402]  48.71 35.31 180 top
CD66  0.22U_0402_6.3V6K  [C_0402]  78.27 33.55 180 top
CD67  0.22U_0402_6.3V6K  [C_0402]  58.54 18.65 0 top
CD68  0.22U_0402_6.3V6K  [C_0402]  41.52 35.39 180 top
CD69  0.22U_0402_6.3V6K  [C_0402]  81.58 16.86 270 top
CD70  0.22U_0402_6.3V6K  [C_0402]  70.26 35.77 0 top
CD71  0.22U_0402_6.3V6K  [C_0402]  52.82 35.48 180 top
CD72  0.22U_0402_6.3V6K  [C_0402]  85.14 25.74 0 top
CD73  0.22U_0402_6.3V6K  [C_0402]  85.13 24.8 0 top
CD74  0.22U_0402_6.3V6K  [C_0402]  85.13 23.2 0 top
CD75  0.22U_0402_6.3V6K  [C_0402]  48.4 18.51 0 top
CD76  0.22U_0402_6.3V6K  [C_0402]  69.88 18.84 0 top
CD77  0.22U_0402_6.3V6K  [C_0402]  68.33 18.36 180 top
CD78  0.22U_0402_6.3V6K  [C_0402]  71.71 18.79 270 top
CD79  0.22U_0402_6.3V6K  [C_0402]  45.27 18.53 180 top
CD80  0.22U_0402_6.3V6K  [C_0402]  64.74 35.51 0 top
CD81  0.22U_0402_6.3V6K  [C_0402]  34.1 21.75 270 bottom
CD82  0.22U_0402_6.3V6K  [C_0402]  30.19 24.69 270 top
CD83  0.22U_0402_6.3V6K  [C_0402]  30.24 26.47 180 top
CD84  0.22U_0402_6.3V6K  [C_0402]  35.02 26.17 180 top
CD85  0.22U_0402_6.3V6K  [C_0402]  30.24 25.58 180 top
CD86  0.22U_0402_6.3V6K  [C_0402]  28.52 19.51 90 bottom
CD87  0.22U_0402_6.3V6K  [C_0402]  32.17 19.56 90 bottom
CD88  0.22U_0402_6.3V6K  [C_0402]  29.43 19.54 90 bottom
CD89  0.22U_0402_6.3V6K  [C_0402]  31.26 19.54 90 bottom
CD90  0.22U_0402_6.3V6K  [C_0402]  30.34 19.54 90 bottom
CD91  0.1U_0201_10V6K  [C_0201]  39.65 20.82 270 bottom
CD92  0.1U_0201_10V6K  [C_0201]  60.1 21.75 0 bottom
CD93  0.1U_0201_10V6K  [C_0201]  73.96 20.82 270 bottom
CD94  0.1U_0201_10V6K  [C_0201]  50.54 20.88 0 bottom
CD95  1U_0201_6.3V6M  [C_0201]  46 20.76 270 bottom
CD96  10U 6.3V M X5R 0402  [C_0402]  46.82 20.97 270 bottom
CD97  1U_0201_6.3V6M  [C_0201]  45.43 20.76 270 bottom
CD98  10U 6.3V M X5R 0402  [C_0402]  57.75 21.06 270 bottom
CD99  1U_0201_6.3V6M  [C_0201]  56.46 20.82 270 bottom
CD100  1U_0201_6.3V6M  [C_0201]  57.03 20.82 270 bottom
CD101  1U_0201_6.3V6M  [C_0201]  68.94 19.93 270 bottom
CD102  1U_0201_6.3V6M  [C_0201]  69.51 19.93 270 bottom
CD103  10U 6.3V M X5R 0402  [C_0402]  70.26 19.83 0 bottom
CD104  1U_0201_6.3V6M  [C_0201]  82.36 16.96 270 top
CD105  1U_0201_6.3V6M  [C_0201]  82.97 16.96 270 top
CD106  10U 6.3V M X5R 0402  [C_0402]  84.22 16.87 270 top
CD107  22U_0603_6.3V6M  [C_0603]  137.52 25.55 270 bottom
CD108  22U_0603_6.3V6M  [C_0603]  135.42 19.51 270 bottom
CD109  0.22U_0402_6.3V6K  [C_0402]  128.57 25.56 270 bottom
CD110  0.22U_0402_6.3V6K  [C_0402]  126.22 24.1 270 bottom
CD111  0.22U_0402_6.3V6K  [C_0402]  109.34 22.69 180 bottom
CD112  0.22U_0402_6.3V6K  [C_0402]  119.47 16.03 180 bottom
CD113  0.22U_0402_6.3V6K  [C_0402]  86.48 21.76 180 top
CD114  0.22U_0402_6.3V6K  [C_0402]  31.07 31.23 0 top
CF1  10U_0402_6.3V6M  [C_0402]  188.32 56.36 270 top
CF2  0.1U_0201_10V6K  [C_0201]  187.18 55.44 90 top
CF3  6.8P_0402_50V8C  [C_0402]  188.7 63.37 90 top
CF4  6.8P_0402_50V8C  [C_0402]  189.69 63.37 90 top
CF5  0.1U_0201_10V6K  [C_0201]  193.21 16.91 270 top
CF6  0.1U_0201_10V6K  [C_0201]  187.76 17.27 135 top
CF7  0.1U_0201_10V6K  [C_0201]  194.8 19.7 180 top
CF8  0.1U_0201_10V6K  [C_0201]  166.41 18.53 270 top
CF9  0.1U_0201_10V6K  [C_0201]  27.89 45.29 180 top
CF10  0.1U_0201_10V6K  [C_0201]  60.94 56.95 270 top
CF11  10P_0402_50V8J  [C_0402]  92.11 82.32 315 top
CF12  10P_0402_50V8J  [C_0402]  88.7 73.23 180 top
CF13  0.1U_0201_10V6K  [C_0201]  197.4 22.52 90 top
CFP1  0.1U_0201_10V K X5R  [C_0201]  105.9 10.18 180 top
CFP2  0.1U_0201_10V K X5R  [C_0201]  112.46 9.86 0 bottom
CFP3  0.1U_0201_10V K X5R  [C_0201]  100.78 8.21 0 top
CFP4  0.1U_0201_10V K X5R  [C_0201]  102.59 10.71 90 top
CH1  0.1U_0201_10V6K  [C_0201]  21.17 67.48 180 bottom
CH2  0.1U_0201_10V6K  [C_0201]  21.17 68.04 180 bottom
CH3  0.1U_0201_10V6K  [C_0201]  21.17 69.11 180 bottom
CH4  0.1U_0201_10V6K  [C_0201]  21.17 69.66 180 bottom
CH5  0.1U_0201_10V6K  [C_0201]  17.17 74.17 270 bottom
CH6  0.1U_0201_10V6K  [C_0201]  21.21 76.05 90 bottom
CH7  0.1U_0201_10V6K  [C_0201]  21.17 65.79 180 bottom
CH8  0.1U_0201_10V6K  [C_0201]  21.17 66.35 180 bottom
CH9  0.1U_0201_10V6K  [C_0201]  21.17 64.15 180 bottom
CH10  0.1U_0201_10V6K  [C_0201]  21.17 64.71 180 bottom
CH11  10P_0402_50V8J  [C_0402]  25.78 70.94 90 bottom
CH12  10P_0402_50V8J  [C_0402]  25.78 73.63 270 bottom
CH13  10P_0402_50V8J  [C_0402]  18.47 72.03 180 bottom
CH14  10P_0402_50V8J  [C_0402]  18.47 70.63 180 bottom
CHDT1  0.01U_0402_16V7K  [C_0402]  150.98 54.36 90 bottom
CHDT2  0.01U_0402_16V7K  [C_0402]  145.52 54.36 90 bottom
CHDT3  0.01U_0402_16V7K  [C_0402]  142.22 44.33 90 bottom
CKBL1  10U_0402_6.3V6M  [C_0402]  142.8 14.05 180 bottom
CKBL2  0.1U_0201_10V6K  [C_0201]  141.99 13.29 0 bottom
CKBL3  0.01U_0402_16V7K  [C_0402]  143.77 13.76 90 top
CLRP1  SHORT PADS  [SHORTPADS]  92.22 9.3 0 bottom
CSD1  0.01U_0402_16V7K  [C_0402]  31.32 38.88 180 top
CSD2  0.1U_0201_10V6K  [C_0201]  31.26 41.93 180 top
CSD3  10U_0402_6.3V6M  [C_0402]  31.32 39.9 180 top
CSD4  10U_0402_6.3V6M  [C_0402]  29.66 21.95 180 bottom
CSD5  0.01U_0402_16V7K  [C_0402]  58.65 56.79 270 top
CSD6  0.1U_0201_10V6K  [C_0201]  56.16 56.85 270 top
CSD7  10U_0402_6.3V6M  [C_0402]  59.69 56.79 270 top
CSD8  10U_0402_6.3V6M  [C_0402]  73.26 58.36 90 top
CSD10  0.1U_0201_10V6K  [C_0201]  33.01 53.18 180 bottom
CSD12  0.1U_0201_10V6K  [C_0201]  41.43 46.98 90 bottom
CT34  0.1U_0402_50V6K  [C_0402]  32.57 81.17 180 top
CT35  0.1U_0201_10V6K  [C_0201]  31.87 85.9 0 top
CT36  0.1U_0201_10V6K  [C_0201]  31.87 86.53 0 top
CT37  220P_0201_25V7K  [C_0201]  31.6 83.98 90 top
CT38  220P_0201_25V7K  [C_0201]  31.6 83.37 270 top
CT43  0.33U_0201_6.3V6M  [C_0201]  101.39 79.16 90 bottom
CT44  0.33U_0201_6.3V6M  [C_0201]  102.02 79.16 90 bottom
CT45  0.33U_0201_6.3V6M  [C_0201]  104.56 79.16 90 bottom
CT46  10U_0402_6.3V6M  [C_0402]  35.03 88.33 180 top
CT47  0.1U_0201_10V6K  [C_0201]  42.7 83.62 270 top
CT48  4.7U_0402_6.3V6M  [C_0402]  43.48 83.71 270 top
CT49  0.33U_0201_6.3V6M  [C_0201]  103.93 79.16 90 bottom
CT50  10U_0402_6.3V6M  [C_0402]  44.39 81.78 0 top
CT51  0.1U_0201_10V6K  [C_0201]  42.65 81.56 270 top
CT52  0.1U_0402_25V7K  [C_0402]  41.05 80.09 0 top
CT53  4.7U_0603_25V6K  [C_0603]  40.62 79.04 270 top
CT54  0.47U_0402_25V6K  [C_0402]  12.75 90.19 180 bottom
CT55  0.47U_0402_25V6K  [C_0402]  12.81 90.14 270 top
CT56  0.47U_0402_25V6K  [C_0402]  12.75 91.08 180 bottom
CT57  0.47U_0402_25V6K  [C_0402]  12.87 91 90 top
CT58  1U_0201_6.3V6M  [C_0201]  29.53 82.31 0 top
CT59  0.1U_0402_50V6K  [C_0402]  25.57 85.16 90 top
CT68  10U_0402_6.3V6M  [C_0402]  26.19 67.33 270 top
CT69  10U_0603_25V6M  [C_0603]  23.92 75.01 180 top
CT70  6800P_0402_25V7K  [C_0402]  21.45 73.68 180 top
CT71  1000P_0402_50V7K  [C_0402]  26.98 72.66 180 top
CT72  0.1U_0201_10V K X5R  [C_0201]  45.48 75.96 180 top
CT73  0.01U_0402_16V7K  [C_0402]  43.49 75.2 180 top
CT74  10U_0402_6.3V6M  [C_0402]  28.88 71.71 180 top
CT75  10U_0603_25V6M  [C_0603]  27.16 81.62 180 top
CT76  0.1U_0402_25V6  [C_0402]  31.66 74.77 270 top
CT77  100P_0402_50V8J  [C_0402]  31.65 79.39 0 top
CT78  6800P_0402_25V7K  [C_0402]  30.78 79.38 90 top
CTP1  0.1U_0201_10V6K  [C_0201]  124.44 10.77 90 bottom
CTP2  100P_0402_50V8J  [C_0402]  139.35 12.72 0 bottom
CTP3  100P_0402_50V8J  [C_0402]  139.37 14.06 0 bottom
CTP4  0.01U_0402_16V7K  [C_0402]  118.06 6.83 180 bottom
CTP5  0.1U_0201_10V K X5R  [C_0201]  147.12 20.34 180 top
CTP7  0.1U_0201_10V K X5R  [C_0201]  133.56 12.27 180 bottom
CTS1  2200P_0402_25V7K  [C_0402]  75.28 15.88 0 bottom
CTS2  2200P_0402_25V7K  [C_0402]  20.44 44.15 180 bottom
CTS3  2200P_0402_25V7K  [C_0402]  173.4 49.97 90 bottom
CTS4  2200P_0402_25V7K  [C_0402]  173.42 52.66 270 bottom
CTS5  0.1U_0201_10V6K  [C_0201]  173.87 49.26 180 bottom
CTS6  2200P_0402_25V7K  [C_0402]  176.24 53.5 0 bottom
CTS7  2200P_0402_25V7K  [C_0402]  98.77 86.37 0 bottom
CUS1  10U_0402_6.3V6M  [C_0402]  194.52 27.93 180 top
CUS2  10U_0402_6.3V6M  [C_0402]  191.71 25.96 90 top
CUS3  10U_0402_6.3V6M  [C_0402]  190.81 26.69 90 top
CUS4  0.1U_0201_10V6K  [C_0201]  198.99 24.59 0 top
CWL1  4.7U_0402_6.3V6M  [C_0402]  171.48 45.61 0 top
CWL2  0.1U_0201_10V K X5R  [C_0201]  171.64 28.21 0 top
CWL9  1U_0201_6.3V6M  [C_0201]  167.58 56.61 90 bottom
CWL61  1U_0201_6.3V6M  [C_0201]  170.53 55.5 90 bottom
D6  AZC399-04S.R7G SOT23-6  [AZC099-04SPR7G_SOT23-6]  51.16 48.21 180 bottom
D33  CEST23LC5VB  [PSOT24C_SOT23-3]  21.67 61.08 270 bottom
DA2  AZC099-04S.R7G_SOT23-6  [AZC099-04SPR7G_SOT23-6]  26.09 4.48 180 bottom
DA3  CEST23LC5VB  [AZ5125-02SPR7G_SOT23-3]  17.62 51.92 270 bottom
DA4  AZ5125-02S.R7G_SOT23-3  [AZ5125-02SPR7G_SOT23-3]  16.06 59.12 0 bottom
DFP1  CEST23LC5VB  [PSOT24C_SOT23-3]  96.97 11.81 0 bottom
DH1  L05ESDL5V0NA-4_SLP2510P8-10-9  [YSCLAMP0524P_SLP2510P8-10-9]  15.16 70.77 90 bottom
DH2  L05ESDL5V0NA-4_SLP2510P8-10-9  [YSCLAMP0524P_SLP2510P8-10-9]  16.04 66.17 270 bottom
DH3  L05ESDL5V0NA-4_SLP2510P8-10-9  [YSCLAMP0524P_SLP2510P8-10-9]  15.16 67.6 90 bottom
DT1  CEST236LC5VU  [AZC099-04SPR7G_SOT23-6]  17.18 92.49 180 bottom
DT6  CEST23NC24VU 3P C/A SOT23  [PESD24VS2UT_SOT23-3]  22.1 85.79 90 top
DT7  AZ124S-04F.R7G  [PUSB3FR4_DFN2510A10-10]  15.13 91.32 270 top
DT8  AZ124S-04F.R7G  [PUSB3FR4_DFN2510A10-10]  15.13 89.32 90 bottom
DT15  -  [NSR20F30NXT5G_DSN2-2]  23.67 73.68 180 top
DT16  CEST236LC5VU  [AZC099-04SPR7G_SOT23-6]  33.87 89.36 270 bottom
DTP1  L03ESDL5V0CC3-2_SOT23-3  [PSOT24C_SOT23-3]  135.46 12.03 90 bottom
FD1  CF  [FIDUCIAL_C40M80]  46.33 88.85 0 top
FD2  CF  [FIDUCIAL_C40M80]  163.17 20.15 0 top
FD3  CF  [FIDUCIAL_C40M80]  166.35 106.44 180 bottom
FD4  CF  [FIDUCIAL_C40M80]  21 17.67 180 bottom
H1  HOLEA  [H_3P3]  131.88 48.76 0 top
H2  HOLEA  [H_3P3]  106.37 89.75 0 top
H3  HOLEA  [H_3P3]  80.86 48.76 0 top
H5  HOLEA  [H_3P2]  197.89 37.3 0 top
H7  HOLEA  [H_3P2]  106.9 34.17 0 top
H8  HOLEA  [H_3P1X2P1N]  7.48 80.3 0 top
H10  HOLEA  [H_2P3]  177.33 107.38 0 top
H11  HOLEA  [H_3P3]  157.43 31.21 0 top
H12  HOLEA  [H_3P5]  190.12 71.4 0 top
H13  HOLEA  [H_2P3]  18.18 39.58 0 top
H14  HOLEA  [H_3P1X2P1N]  10.93 45.68 0 top
H15  HOLEA  [H_2P3]  94.92 4.34 0 top
H16  HOLEA  [H_2P8]  13.43 82.75 0 top
H17  HOLEA  [H_2P1N]  171.43 107.65 0 top
H18  HOLEA  [H_3P2]  64.91 94.28 180 bottom
J1  -  [JUMP_43X79]  53.31 97.51 270 bottom
J2  -  [JUMP_43X79]  46.7 91.66 0 bottom
J5  -  [JUMP_43X79]  154.49 67.22 45 bottom
J6  -  [JUMP_43X79]  149.52 73.03 45 bottom
JBATT1  ACES_60757-00802-001  [ACES_60757-00802-001_8P-T]  79.39 14.04 180 bottom
JDCIN1  ACES_50278-00401-001  [ACES_50278-00401-001_4P]  22.58 76.75 0 bottom
JEDP1  ACES 50398-04041-001  [CVILU_CVS3402M1RM-NH_40P]  50.76 76.01 270 bottom
JFAN2  HEFENG AWB03-S04C1A-HF  [JXT_WB201H-004G10M_4P]  187.16 50.25 0 bottom
JFP1  ACES_51522-00801-001  [ACES_51522-00801-001_8P]  106.07 11.99 180 bottom
JHDMI1  HEFENG HHF-14A000-2DB  [LOTES_AHDM0064-P001A_19P]  10.37 65.73 90 bottom
JHDT1  SAMTE_ASP-136446-07-B  [SAMTE_ASP-136446-07-B_20P-T]  154.35 47.77 180 bottom
JIO1  HRS_TF31-40S-0P5SH(800)  [HRS_TF31-40S-0P5SH-800_40P]  203.31 28.78 210.8 bottom
JKB2  ACES_51612-0340M-P01  [ACES_51612-0340M-P01_34P-T]  180.59 20.63 180 bottom
JKBL1  JXT FP202DH-004G10M  [ACES_51524-00401-001_4P]  146.36 11.57 180 bottom
JP1  SHORT PADS  [SHORTPADS]  190.22 52.34 270 top
JP2  SHORT PADS  [SHORTPADS]  195.05 51.83 270 bottom
JP3  YUQIU_1603046-01611  [YUQIU_1603046-01611_6P]  1.93 49.13 90 bottom
JSPK1  ACES_50271-0040N-001  [ACES_50271-0040N-001_4P]  33.86 8.6 180 bottom
JSSD1  BELLW_80159-3221  [BELLW_80159-3221_67P]  23.37 43.41 270 bottom
JSSD2  BELLW_80159-3221  [BELLW_80159-3221_67P]  55.66 48.75 0 bottom
JTP1  ACES_51522-00801-001  [ACES_51522-00801-001_8P]  131.53 11.99 180 bottom
JUSBC2  HIGHSTAR UB11249-B200G-1H  [DRAPH_UB11245-B200B-1H_24P-S]  8.82 86.75 90 bottom
JWLAN1  BELLW_80152-3221  [BELLW_80152-3221_67P]  164.36 46.55 270 bottom
L1  BLM15AX601SN1D_0402_2P  [MURAT_BLM15AX300SN1D_2P]  193.82 30.55 180 top
L2  BLM15AX601SN1D_0402_2P  [MURAT_BLM15AX300SN1D_2P]  193.8 32.61 180 top
LED2  LTW-C193TS5-C_WHITE  [LED_LTW-C193TS5-C_2P]  5.51 99.8 0 top
LED3  LTST-C191KFKT-2CA_ORANGE  [LED_LTST-C191KFKT-2CA_2P]  5.51 98 0 top
LED4  LTW-S110DC2-C WHITE  [LED_LTW-110DC5-C_3P]  3.49 32.68 90 top
LH1  HCM1012GH900BP_4P  [INPAQ_HCM1012GH900BP_4P]  18.4 68.1 180 bottom
LH2  HCM1012GH900BP_4P  [INPAQ_HCM1012GH900BP_4P]  18.38 69.6 180 bottom
LH3  HCM1012GH900BP_4P  [INPAQ_HCM1012GH900BP_4P]  18.41 66.16 180 bottom
LH4  HCM1012GH900BP_4P  [INPAQ_HCM1012GH900BP_4P]  18.42 64.67 180 bottom
LT1  DLM0NSN900HY2D_4P  [MURAT_DLM0NSN900HY2D_4P]  19.07 93.99 180 bottom
NOREF  -  []  131.88 48.76 0 top
NOREF#2  -  []  106.9 34.17 0 top
NOREF#3  -  []  80.86 48.76 0 top
NOREF#4  -  []  13.43 82.75 0 top
NOREF#5  -  []  -62.79 -163.91 0 top
NOREF#6  -  []  64.91 94.28 0 top
NOREF#7  -  []  190.12 71.4 0 top
NOREF#8  -  []  94.92 4.34 180 top
NOREF#9  -  []  197.89 37.3 270 top
NOREF#10  -  []  52.78 105.15 0 top
NOREF#11  -  []  34.72 47.07 0 top
NOREF#12  -  []  18.18 39.58 0 top
NOREF#13  -  []  67.9 37.58 0 top
NOREF#14  -  []  157.43 31.21 0 top
NOREF#15  -  []  147.43 116.35 0 top
NOREF#16  -  []  91.4 38.41 0 top
NOREF#17  -  []  177.33 107.38 0 top
NOREF#18  -  []  106.37 89.75 0 top
NOREF#19  -  []  116.81 40.08 0 top
NOREF#20  -  []  69.2 -52.37 0 top
NOREF#21  -  []  142.79 39.58 180 bottom
NOREF#22  -  []  70.29 39.85 180 bottom
NOREF#23  -  []  63.94 105.94 180 bottom
NOREF#24  -  []  152.66 87.42 180 bottom
NOREF#25  -  []  174.53 96.82 180 bottom
NOREF#26  -  []  53.75 39.57 180 bottom
PC10  1000P_0402_50V7K  [C_0402]  76.56 5.3 270 bottom
PC11  0.01U_0402_25V7K  [C_0402]  76.56 2.61 90 bottom
PC251  2.2U_0402_10V6M  [C_0402]  120.51 11.45 180 top
PC253  10U_0603_6.3V6M  [C_0603]  120.88 9.12 90 top
PC255  0.1U_0402_16V7K  [C_0402]  121.05 8.08 0 top
PC256  10U_0402_6.3V6M  [C_0402]  114.81 9.4 90 top
PC257  10U_0402_6.3V6M  [C_0402]  113.87 9.4 90 top
PC301  0.1U_0402_25V6  [C_0402]  178.53 64.34 315 top
PC302  0.1U_0402_25V6  [C_0402]  179.53 68.17 135 bottom
PC303  2200P_0402_50V7K  [C_0402]  179.54 68.18 135 top
PC304  10U_0603_25V6M  [C_0603]  180.29 69.06 135 top
PC305  10U_0603_25V6M  [C_0603]  180.27 69.04 135 bottom
PC306  22U_0603_6.3V6M  [C_0603]  175.54 60.29 315 bottom
PC307  22U_0603_6.3V6M  [C_0603]  177.37 60.01 45 bottom
PC308  22U_0603_6.3V6M  [C_0603]  173.79 58.56 315 bottom
PC309  22U_0603_6.3V6M  [C_0603]  174.66 59.43 315 bottom
PC310  4.7U_0402_6.3V6M  [C_0402]  171.82 67.61 225 top
PC311  4.7U_0402_6.3V6M  [C_0402]  172.54 66.89 225 top
PC312  680P_0402_50V7K  [C_0402]  173.9 62.42 135 top
PC313  1000P_0402_50V7K  [C_0402]  173.73 70.79 135 top
PC501  0.1U_0402_25V6  [C_0402]  34.25 17.72 270 bottom
PC502  10U_0603_25V6M  [C_0603]  41.76 15 270 top
PC503  10U_0603_25V6M  [C_0603]  41.76 15 270 bottom
PC504  10U_0603_25V6M  [C_0603]  40.49 15 270 bottom
PC505  10U_0603_25V6M  [C_0603]  40.49 15 270 top
PC506  2200P_0402_50V7K  [C_0402]  39.4 14.95 270 top
PC507  0.1U_0402_25V6  [C_0402]  39.4 14.95 270 bottom
PC508  4.7U_0402_6.3V6M  [C_0402]  34.38 11.07 180 bottom
PC509  22U_0603_6.3V6M  [C_0603]  22.58 12.72 180 bottom
PC510  22U_0603_6.3V6M  [C_0603]  27.56 10.91 0 top
PC511  22U_0603_6.3V6M  [C_0603]  22.58 11.45 180 bottom
PC512  22U_0603_6.3V6M  [C_0603]  24.27 12.39 180 top
PC513  22U_0603_6.3V6M  [C_0603]  24.26 10.95 180 top
PC514  22U_0603_6.3V6M  [C_0603]  22.58 10.18 180 bottom
PC515  22U_0603_6.3V6M  [C_0603]  27.56 12.3 0 top
PC516  22U_0603_6.3V6M  [C_0603]  22.58 13.99 180 bottom
PC517  680P_0402_50V7K  [C_0402]  30.37 10.93 90 top
PC518  4.7U_0402_6.3V6M  [C_0402]  34.38 10.17 180 bottom
PC519  1000P_0402_25V8J  [C_0402]  36.4 11.07 0 bottom
PC520  1U_0402_6.3V6K  [C_0402]  176.37 71.01 135 top
PC521  4.7U_0402_6.3V6M  [C_0402]  169.9 66.92 315 top
PC522  4.7U_0402_6.3V6M  [C_0402]  174.3 71.48 45 top
PC601  2200P_0402_50V7K  [C_0402]  163.24 95.16 315 top
PC602  0.1U_0603_25V7K  [C_0603]  155.49 94.49 225 bottom
PC603  680P_0402_50V7K  [C_0402]  150.93 92.42 45 bottom
PC604  0.1U_0402_25V6  [C_0402]  164.62 96.8 315 bottom
PC605  10U_0603_25V6M  [C_0603]  162.82 95.37 315 bottom
PC606  22U_0603_6.3V6M  [C_0603]  157.21 82.87 315 bottom
PC607  22U_0603_6.3V6M  [C_0603]  158.1 83.76 315 bottom
PC608  22U_0603_6.3V6M  [C_0603]  159.03 84.69 315 bottom
PC609  22U_0603_6.3V6M  [C_0603]  156.17 81.91 315 bottom
PC610  22U_0603_6.3V6M  [C_0603]  154.21 79.94 315 bottom
PC611  22U_0603_6.3V6M  [C_0603]  155.15 80.89 315 bottom
PC612  4.7U_0402_6.3V6M  [C_0402]  160.08 88.08 225 bottom
PC613  330P_0402_50V7K  [C_0402]  159.97 85.46 315 bottom
PC614  0.22U_0402_10V6K  [C_0402]  165.02 90.88 315 bottom
PC615  2.2U_0402_6.3V6M  [C_0402]  162.01 87.87 315 bottom
PC622  10U_0603_25V6M  [C_0603]  163.68 96.21 315 bottom
PC623  0.1U_0402_25V6  [C_0402]  162.05 94.61 315 bottom
PC715  2200P_0402_50V7K  [C_0402]  170.25 83.78 315 bottom
PC716  0.1U_0402_25V6  [C_0402]  171.9 85.24 315 bottom
PC717  0.1U_0402_25V6  [C_0402]  166.16 80.73 315 bottom
PC718  10U_0603_25V6M  [C_0603]  171.1 84.55 315 bottom
PC719  330P_0402_50V7K  [C_0402]  171.46 75.1 45 bottom
PC724  4.7U_0402_6.3V6M  [C_0402]  169.36 75.86 225 bottom
PC726  2.2U_0402_6.3V6M  [C_0402]  170.05 75.18 315 bottom
PC801  330P_0402_50V7K  [C_0402]  106.75 96.22 180 bottom
PC802  0.01U_0402_50V7K  [C_0402]  105.3 95.33 270 bottom
PC803  10U_0603_25V6M  [C_0603]  110.99 103.05 0 top
PC804  10U_0603_25V6M  [C_0603]  136.03 98.89 0 top
PC805  0.22U_0603_25V7K  [C_0603]  95.38 104.4 270 bottom
PC806  0.1U_0402_25V6  [C_0402]  92.13 98.71 180 bottom
PC807  470P_0402_50V7K  [C_0402]  102.38 96.55 270 top
PC808  68P_0402_50V8J  [C_0402]  102.4 94.8 270 top
PC809  0.1U_0402_25V6  [C_0402]  111.18 104.13 0 top
PC810  2200P_0402_50V7K  [C_0402]  135.92 100.35 0 top
PC811  680P_0402_50V7K  [C_0402]  77.72 97.42 90 top
PC812  0.1U_0402_25V6  [C_0402]  90.32 98.77 270 bottom
PC813  1U_0402_6.3V6K  [C_0402]  98.97 94.33 270 top
PC814  2.2U_0603_10V6K  [C_0603]  92.18 91.29 180 top
PC815  2.2U_0603_10V6K  [C_0603]  99.56 103.04 90 bottom
PC816  0.1U_0402_25V6  [C_0402]  141.28 100.37 180 bottom
PC817  2200P_0402_50V7K  [C_0402]  141.28 100.35 180 top
PC818  10U_0603_25V6M  [C_0603]  86.71 100.45 270 top
PC819  10U_0603_25V6M  [C_0603]  86.71 100.45 270 bottom
PC820  33U_25V_NC_6.3X4.5  [C_6P3X4P5]  135.74 104.92 0 bottom
PC821  0.1U_0402_25V6  [C_0402]  135.92 100.39 0 bottom
PC822  2200P_0402_50V7K  [C_0402]  111.18 104.13 0 bottom
PC824  0.22U_0603_25V7K  [C_0603]  100.94 104.42 270 bottom
PC825  0.1U_0402_25V6  [C_0402]  104.03 100.59 0 bottom
PC826  680P_0402_50V7K  [C_0402]  119.74 95.83 90 top
PC827  0.47U_0402_6.3V6K  [C_0402]  98.32 91.6 270 bottom
PC828  0.47U_0402_6.3V6K  [C_0402]  99.27 91.6 270 bottom
PC829  68P_0402_50V8J  [C_0402]  92.13 93.29 90 bottom
PC830  390P_0402_50V7K  [C_0402]  92.13 95.07 90 bottom
PC831  0.1U_0402_25V6  [C_0402]  92.19 97.79 180 top
PC832  0.1U_0402_25V6  [C_0402]  108.25 99.09 270 bottom
PC833  330P_0402_50V7K  [C_0402]  92.13 96.87 180 bottom
PC834  33U_25V_NC_6.3X4.5  [C_6P3X4P5]  123.17 106.45 270 bottom
PC838  0.01U_0402_50V7K  [C_0402]  90.32 96.91 90 top
PC839  10U_0603_25V6M  [C_0603]  110.99 103.05 0 bottom
PC840  10U_0603_25V6M  [C_0603]  136.03 98.89 0 bottom
PC841  0.22U_0603_25V7K  [C_0603]  98.08 104.42 270 bottom
PC842  0.1U_0402_25V6  [C_0402]  104.21 98 0 bottom
PC843  680P_0402_50V7K  [C_0402]  129.4 96.14 180 top
PC844  0.1U_0402_25V6  [C_0402]  105.96 97.97 0 bottom
PC845  1U_0603_10V6K  [C_0603]  149.27 103.14 90 top
PC846  0.22U_0603_25V7K  [C_0603]  144.17 104.75 0 bottom
PC847  10U_0603_25V6M  [C_0603]  141.18 98.88 180 bottom
PC848  10U_0603_25V6M  [C_0603]  141.18 98.88 180 top
PC849  680P_0402_50V7K  [C_0402]  149.46 95.19 90 top
PC850  0.1U_0402_25V6  [C_0402]  105.76 97.11 0 top
PC851  0.1U_0402_25V6  [C_0402]  107.56 97.17 270 top
PC852  0.022U_0402_25V7K  [C_0402]  98.42 91.47 270 top
PC853  10P_0402_25V8J  [C_0402]  95.15 90.56 90 top
PC854  10P_0402_25V8J  [C_0402]  86.73 55.35 180 bottom
PC855  10P_0402_25V8J  [C_0402]  86.73 56.98 180 bottom
PC1807  22U_0603_6.3V6M  [C_0603]  166.32 73.04 315 bottom
PC1808  0.1U_0402_10V7K  [C_0402]  165.58 72.22 315 bottom
PC9001  22U_0603_6.3V6M  [C_0603]  106.28 63.53 180 top
PC9002  22U_0603_6.3V6M  [C_0603]  106.27 64.74 180 top
PC9003  22U_0603_6.3V6M  [C_0603]  92.15 66.9 180 top
PC9004  22U_0603_6.3V6M  [C_0603]  108.12 62.88 0 top
PC9005  22U_0603_6.3V6M  [C_0603]  108.12 64.13 0 top
PC9006  22U_0603_6.3V6M  [C_0603]  108.12 65.39 0 top
PC9007  22U_0603_6.3V6M  [C_0603]  143.62 88.22 0 top
PC9008  22U_0603_6.3V6M  [C_0603]  91.01 72.79 180 top
PC9009  22U_0603_6.3V6M  [C_0603]  102.82 73.11 0 top
PC9010  22U_0603_6.3V6M  [C_0603]  143.81 90.32 0 top
PC9011  22U_0603_6.3V6M  [C_0603]  78.96 84.85 180 top
PC9012  22U_0603_6.3V6M  [C_0603]  78.96 86.11 180 top
PC9013  22U_0603_6.3V6M  [C_0603]  104.85 61.6 0 top
PC9014  22U_0603_6.3V6M  [C_0603]  99.9 61.32 180 top
PC9015  22U_0603_6.3V6M  [C_0603]  93.17 84.17 0 top
PC9016  22U_0603_6.3V6M  [C_0603]  93.16 86.66 0 top
PC9017  22U_0603_6.3V6M  [C_0603]  97.54 61.57 180 top
PC9018  22U_0603_6.3V6M  [C_0603]  103.1 61.57 180 top
PC9019  22U_0603_6.3V6M  [C_0603]  103.08 62.81 180 top
PC9020  22U_0603_6.3V6M  [C_0603]  93.16 85.4 0 top
PC9021  220U_D7_2VM_R4.5M  [C_D7]  109.71 68.64 90 top
PC9029  22U_0603_6.3V6M  [C_0603]  106.29 65.94 180 top
PC9030  22U_0603_6.3V6M  [C_0603]  106.3 67.13 180 top
PC9031  22U_0603_6.3V6M  [C_0603]  106.53 68.41 180 top
PC9032  22U_0603_6.3V6M  [C_0603]  94.15 74.74 180 top
PC9033  22U_0603_6.3V6M  [C_0603]  111.19 63.14 0 top
PC9034  22U_0603_6.3V6M  [C_0603]  111.17 64.34 0 top
PC9035  22U_0603_6.3V6M  [C_0603]  111.17 65.55 0 top
PC9036  22U_0603_6.3V6M  [C_0603]  143.62 86.95 0 top
PC9037  22U_0603_6.3V6M  [C_0603]  92.6 65.68 180 top
PC9038  22U_0603_6.3V6M  [C_0603]  148.19 88.09 0 bottom
PC9039  22U_0603_6.3V6M  [C_0603]  84.45 86.23 0 top
PC9040  22U_0603_6.3V6M  [C_0603]  78.96 87.35 180 top
PC9041  22U_0603_6.3V6M  [C_0603]  84.45 91.3 0 top
PC9042  22U_0603_6.3V6M  [C_0603]  84.45 84.97 0 top
PC9043  22U_0603_6.3V6M  [C_0603]  84.45 87.49 0 top
PC9044  22U_0603_6.3V6M  [C_0603]  84.45 90.03 0 top
PC9045  22U_0603_6.3V6M  [C_0603]  84.45 88.77 0 top
PC9046  22U_0603_6.3V6M  [C_0603]  101.71 74.31 0 top
PC9047  22U_0603_6.3V6M  [C_0603]  103.06 65.35 180 top
PC9048  22U_0603_6.3V6M  [C_0603]  103.06 66.57 180 top
PC9049  22U_0603_6.3V6M  [C_0603]  103.06 67.79 180 top
PC9050  22U_0603_6.3V6M  [C_0603]  103.06 69.01 180 top
PC9051  22U_0603_6.3V6M  [C_0603]  92.15 68.09 180 top
PC9052  22U_0603_6.3V6M  [C_0603]  93.79 66.34 0 top
PC9053  22U_0603_6.3V6M  [C_0603]  84.45 83.7 0 top
PC9056  0.22U_0402_16V7K  [C_0402]  111.09 60.85 0 top
PC9057  0.22U_0402_16V7K  [C_0402]  106.9 70.08 90 top
PC9058  0.22U_0402_16V7K  [C_0402]  112.49 76.54 0 top
PC9059  0.22U_0402_16V7K  [C_0402]  118.2 83.91 270 bottom
PC9060  0.22U_0402_16V7K  [C_0402]  119.15 83.91 270 bottom
PC9061  0.22U_0402_16V7K  [C_0402]  117.18 83.91 270 bottom
PC9062  0.22U_0402_16V7K  [C_0402]  121.06 83.91 270 bottom
PC9063  0.22U_0402_16V7K  [C_0402]  120.12 83.91 270 bottom
PC9064  0.22U_0402_16V7K  [C_0402]  105.5 60.53 0 top
PC9065  0.22U_0402_16V7K  [C_0402]  79.03 91.3 180 top
PC9066  0.22U_0402_16V7K  [C_0402]  79.03 90.35 180 top
PC9067  0.22U_0402_16V7K  [C_0402]  79.03 88.44 180 top
PC9068  0.22U_0402_16V7K  [C_0402]  103.37 60.18 0 top
PC9069  0.22U_0402_16V7K  [C_0402]  102.53 60.23 180 top
PC9070  0.22U_0402_16V7K  [C_0402]  105.58 59.62 0 top
PC9071  0.22U_0402_16V7K  [C_0402]  78.85 83.79 180 top
PC9081  180P_0402_50V8J  [C_0402]  147.77 87.05 0 bottom
PC9082  180P_0402_50V8J  [C_0402]  79.03 89.4 180 top
PC9094  330U_D2_2V_Y  [C_X]  119.26 86.76 180 bottom
PC9095  330U_D2_2V_Y  [C_X]  139.35 85.24 0 bottom
PC9096  220U_D7_2VM_R4.5M  [C_D7]  115.54 79.2 0 top
PC9097  330U_D2_2V_Y  [C_D2]  138.41 89.66 90 bottom
PC9098  330U_D2_2V_Y  [C_X]  123.8 89.53 90 bottom
PC9099  330U_D2_2V_Y  [C_D2]  89.17 85.92 0 bottom
PC9100  330U_D2_2V_Y  [C_D2]  85 85.92 180 bottom
PC9102  0.22U_0402_16V7K  [C_0402]  173.34 78.31 315 bottom
PC9103  680P_0402_50V7K  [C_0402]  163.74 78.51 225 bottom
PC9104  22U_0603_6.3V6M  [C_0603]  167.17 73.95 315 bottom
PC9105  22U_0603_6.3V6M  [C_0603]  111.17 61.93 0 top
PC9106  22U_0603_6.3V6M  [C_0603]  101.88 73.11 180 top
PC9107  22U_0603_6.3V6M  [C_0603]  92.48 70.3 180 top
PC9108  22U_0603_6.3V6M  [C_0603]  95.83 71.71 90 top
PC9109  22U_0603_6.3V6M  [C_0603]  103.05 64.13 180 top
PC9110  22U_0603_6.3V6M  [C_0603]  108.11 61.63 0 top
PC9111  22U_0603_6.3V6M  [C_0603]  97.93 75.4 180 top
PC9112  22U_0603_6.3V6M  [C_0603]  106.87 74.85 180 top
PC9115  220U_D7_2VM_R4.5M  [C_D7]  139.56 89.7 90 top
PC9116  220U_D7_2VM_R4.5M  [C_D7]  98.8 64.4 90 top
PC9117  220U_D7_2VM_R4.5M  [C_D7]  99.05 78.44 180 top
PC9118  330U_D2_2V_Y  [C_X]  128.93 85.87 0 bottom
PC9119  0.1U_0402_25V6  [C_0402]  105.96 102.14 270 bottom
PCB1  0.1U_0402_25V6  [C_0402]  54.77 10.69 90 bottom
PCB2  2200P_0402_25V7K  [C_0402]  55.78 10.69 90 bottom
PCB3  10U_0603_25V6M  [C_0603]  59.86 4.13 270 bottom
PCB4  10U_0603_25V6M  [C_0603]  58.58 4.25 270 bottom
PCB5  10U_0603_25V6M  [C_0603]  56.01 4.25 270 bottom
PCB6  10U_0603_25V6M  [C_0603]  57.31 4.25 270 bottom
PCB7  0.1U_0402_25V6  [C_0402]  51.82 8.82 90 bottom
PCB8  0.033U_0402_25V7K  [C_0402]  52.73 8.4 0 bottom
PCB9  0.033U_0402_25V7K  [C_0402]  52.73 9.8 0 bottom
PCB10  10U_0603_25V6M  [C_0603]  71.16 14.12 0 top
PCB11  0.047U_0402_25V7K  [C_0402]  50.02 11.5 90 bottom
